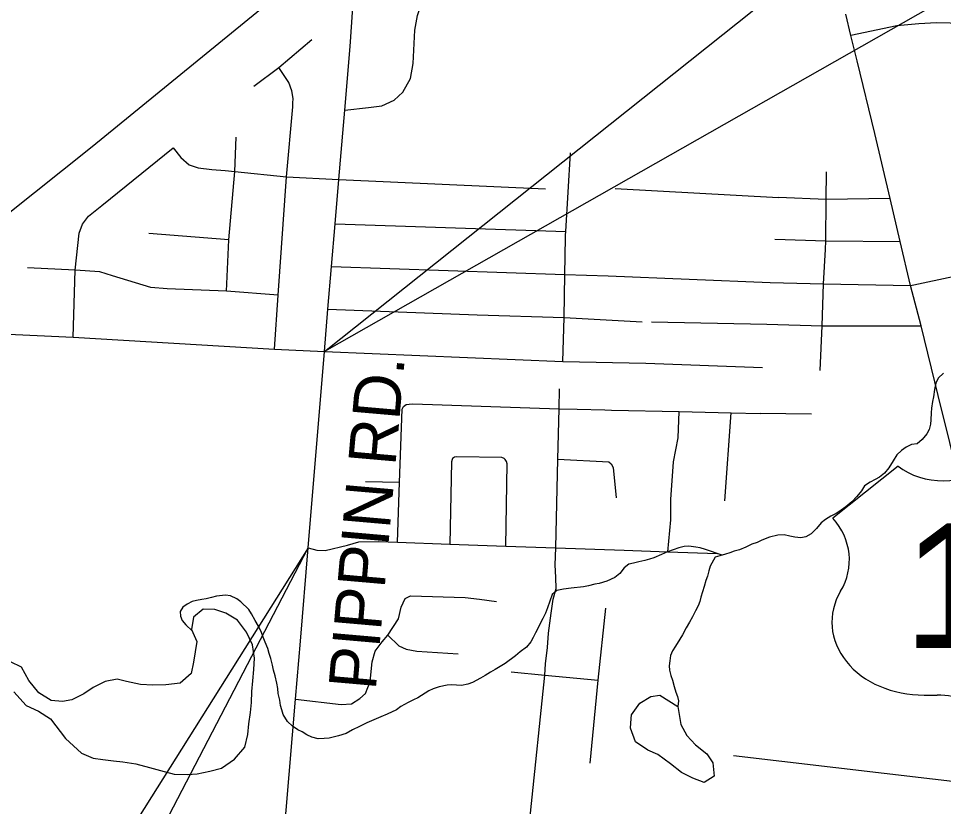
# Model space of a CAD drawing. Extents: x 0 to 34, y 0 to 22.
# Drawn here: x 4.878 to 5.853, y 18.558 to 19.39 of the extents above; entities that cross this region are included whole.
import ezdxf

# ---------------------------------------------------------------- set-up
doc = ezdxf.new("R2010")
doc.units = 0
for name, color, linetype in [('GM_X_County_Road', 7, 'Continuous'), ('GM_X_Interstate_Route', 7, 'Continuous'), ('GM_X_Minor_Lake', 7, 'Continuous'), ('GM_X_Minor_River', 7, 'Continuous'), ('GM_X_Township_ROW', 7, 'Continuous'), ('GM_X_Township_Subdivision', 7, 'Continuous'), ('GM_X_US_Location', 7, 'Continuous'), ('GM_X_US_Route', 7, 'Continuous'), ('GM_X_US_Shield', 7, 'Continuous'), ('RD_P_Text', 7, 'Continuous'), ('SH_Data', 7, 'Continuous')]:
    doc.layers.add(name, color=color, linetype=linetype)

msp = doc.modelspace()

# ---------------------------------------------------------------- linework, layer by layer
at = {"layer": 'GM_X_County_Road'}
for points in [[(5.22032, 19.27679), (5.22169, 19.29301), (5.22737, 19.36039), (5.23583, 19.48408), (5.24687, 19.56925), (5.2531, 19.59368), (5.26696, 19.62416), (5.29814, 19.67508), (5.31221, 19.7074), (5.32012, 19.73072), (5.32457, 19.76478), (5.32835, 19.81159), (5.32927, 19.82298)], [(5.22169, 19.29301), (5.24666, 19.29579), (5.26074, 19.29765), (5.27381, 19.30371), (5.28317, 19.31216), (5.29118, 19.32636), (5.29393, 19.34224), (5.29577, 19.37751), (5.29851, 19.39301), (5.30394, 19.40956), (5.31396, 19.4275), (5.32432, 19.4439), (5.33767, 19.45908), (5.35705, 19.47331), (5.60532, 19.65996), (5.61377, 19.66351), (5.62561, 19.66657), (5.64155, 19.66723), (5.7177, 19.66432)], [(5.15003, 18.43713), (5.16975, 18.67126), (5.17494, 18.73275), (5.18306, 18.83102), (5.20023, 19.03841), (5.20397, 19.0829), (5.20779, 19.12823), (5.21159, 19.17326), (5.21554, 19.22002), (5.22032, 19.27679)], [(4.72311, 18.96889), (4.8302, 18.963), (4.8342, 18.9639), (4.83656, 18.96426), (4.8395, 18.96616), (4.8421, 18.9698), (4.84348, 18.97638), (4.84261, 19.04558), (4.84288, 19.04886), (4.84374, 19.05095), (4.84521, 19.05293), (4.84851, 19.05588), (4.85379, 19.057), (4.85942, 19.057), (4.93528, 19.05337), (5.14755, 19.04076), (5.20023, 19.03841)]]:
    msp.add_lwpolyline(points, dxfattribs=at)
at = {"layer": 'GM_X_Interstate_Route'}
msp.add_lwpolyline([(4.36882, 18.49655), (4.39605, 18.53637), (4.4605, 18.66986), (4.5302, 18.81816), (4.56505, 18.88063), (4.60057, 18.93093), (4.64857, 18.98913), (4.70519, 19.04965), (4.77056, 19.1075), (4.95535, 19.25481), (5.23583, 19.48408)], dxfattribs=at)
at = {"layer": 'GM_X_Minor_Lake'}
for points in [[(4.92715, 18.62971), (4.94392, 18.61453), (4.95634, 18.60895), (4.96656, 18.6076), (4.97793, 18.60623), (4.98778, 18.60527), (5.00141, 18.60309), (5.01577, 18.59938), (5.02747, 18.5961), (5.04183, 18.59238), (5.05587, 18.59172), (5.06614, 18.59265), (5.07949, 18.59543), (5.09171, 18.5986), (5.10558, 18.60822), (5.11647, 18.62055), (5.11941, 18.63419), (5.1204, 18.6452), (5.12217, 18.65734), (5.12353, 18.66797), (5.12377, 18.67938), (5.12476, 18.69077), (5.12577, 18.70255), (5.1264, 18.71471), (5.12441, 18.72883), (5.11824, 18.74227), (5.10862, 18.75465), (5.09624, 18.76212), (5.08455, 18.76617), (5.0724, 18.76641), (5.06235, 18.75786), (5.06018, 18.74497), (5.06562, 18.7323), (5.06212, 18.71031)], [(5.06212, 18.71031), (5.0596, 18.69856), (5.04799, 18.68814), (5.03315, 18.68654), (5.01946, 18.68606), (5.00618, 18.68671), (4.99144, 18.69005), (4.98162, 18.69253), (4.96904, 18.69012), (4.95637, 18.68353), (4.94635, 18.67688), (4.93369, 18.67067), (4.92416, 18.66896), (4.91203, 18.66997), (4.89891, 18.67823), (4.88854, 18.69099), (4.88086, 18.70523), (4.8692, 18.71079)], [(4.87272, 18.67914), (4.88572, 18.6648), (4.8985, 18.65883), (4.91125, 18.65058), (4.92715, 18.62971)], [(5.52404, 18.65105), (5.52412, 18.65485), (5.53311, 18.66721), (5.54465, 18.67419), (5.55418, 18.67552), (5.57308, 18.66349)], [(5.57308, 18.66349), (5.57634, 18.64467), (5.58256, 18.63314), (5.59186, 18.62307), (5.60383, 18.61371), (5.61009, 18.60408), (5.61132, 18.59), (5.60092, 18.58337), (5.58886, 18.58817), (5.57683, 18.59412), (5.56523, 18.60309), (5.55213, 18.61286), (5.54159, 18.61763), (5.52847, 18.62626), (5.52307, 18.64081), (5.52404, 18.65105)]]:
    msp.add_lwpolyline(points, dxfattribs=at)
at = {"layer": 'GM_X_Minor_River'}
for points in [[(5.85352, 19.01542), (5.84772, 19.01021), (5.84534, 19.00493), (5.84406, 18.99811), (5.84277, 18.99053), (5.84191, 18.9856), (5.84063, 18.9784), (5.84053, 18.97346), (5.84, 18.96624), (5.83953, 18.96169), (5.83827, 18.95601), (5.8359, 18.95149), (5.83085, 18.94551), (5.82544, 18.94105), (5.81973, 18.94003), (5.81398, 18.93748), (5.80897, 18.93377), (5.80433, 18.9293), (5.8004, 18.92291), (5.79569, 18.9154), (5.79103, 18.90979), (5.78601, 18.9057), (5.7814, 18.90313), (5.77603, 18.90058), (5.76988, 18.89652), (5.76674, 18.89126), (5.76206, 18.88526), (5.75663, 18.87967), (5.75045, 18.87447), (5.74544, 18.87076), (5.74006, 18.86744), (5.73469, 18.86451), (5.72893, 18.8612), (5.7243, 18.85749), (5.71924, 18.85151), (5.71381, 18.84591), (5.70805, 18.8426), (5.70272, 18.84157), (5.69666, 18.84245), (5.69136, 18.84331), (5.68532, 18.84495), (5.67848, 18.84433)], [(5.67848, 18.84433), (5.66971, 18.84223), (5.66167, 18.83934), (5.65669, 18.83678), (5.65134, 18.83498), (5.64482, 18.83169), (5.63831, 18.82916), (5.63259, 18.82775), (5.628, 18.82594), (5.62342, 18.82451), (5.61731, 18.82273), (5.61234, 18.82131), (5.60722, 18.8119), (5.60598, 18.80698), (5.60435, 18.80131), (5.60273, 18.79677), (5.60108, 18.79034), (5.59907, 18.78468), (5.59744, 18.77901), (5.59621, 18.77446), (5.5946, 18.76993), (5.59183, 18.76466), (5.58867, 18.75826), (5.58552, 18.75262), (5.58198, 18.7466), (5.57803, 18.73945), (5.57528, 18.73457), (5.57058, 18.72743), (5.56744, 18.72255), (5.56545, 18.71765), (5.56457, 18.71196), (5.56408, 18.70664), (5.56437, 18.70207), (5.56577, 18.69634), (5.56757, 18.69136), (5.56934, 18.68486), (5.57111, 18.67874), (5.57292, 18.67414), (5.57396, 18.66955), (5.57308, 18.66349)], [(5.61987, 18.82348), (5.60226, 18.8295), (5.5966, 18.83113), (5.59206, 18.83198), (5.58487, 18.83288), (5.57993, 18.8326), (5.5742, 18.83119), (5.56235, 18.82687), (5.55584, 18.82395), (5.5478, 18.82069), (5.54321, 18.81926), (5.53825, 18.81784), (5.53215, 18.81644), (5.52643, 18.81503), (5.52147, 18.81399), (5.51645, 18.80991), (5.51178, 18.80391), (5.50676, 18.79983), (5.49833, 18.79581), (5.49031, 18.79331), (5.48574, 18.79264), (5.47887, 18.79087), (5.47353, 18.78984), (5.4606, 18.78858), (5.45261, 18.7876), (5.44537, 18.78622), (5.44072, 18.78175), (5.43793, 18.77496), (5.43551, 18.76778), (5.43349, 18.76211), (5.43072, 18.75646), (5.42282, 18.74141), (5.42045, 18.73651), (5.41808, 18.73199), (5.41341, 18.72638), (5.40685, 18.72119), (5.40183, 18.7171), (5.39104, 18.70895), (5.38028, 18.7027), (5.37567, 18.69975), (5.36991, 18.69644), (5.36491, 18.6935), (5.35647, 18.6891), (5.3515, 18.6873), (5.34502, 18.68591), (5.33971, 18.68601), (5.3344, 18.6865), (5.32984, 18.68621), (5.32146, 18.68448), (5.31496, 18.68232), (5.31036, 18.68013), (5.29882, 18.67276), (5.29422, 18.67056), (5.28848, 18.66802), (5.2808, 18.66361), (5.27617, 18.66027), (5.26659, 18.65552), (5.2597, 18.65262), (5.24515, 18.64644), (5.23747, 18.64241), (5.22981, 18.63914), (5.22328, 18.63509), (5.21526, 18.63258), (5.20534, 18.63012), (5.20002, 18.62984), (5.19356, 18.62959), (5.18714, 18.63124), (5.18188, 18.63363), (5.177, 18.63677), (5.17212, 18.63915), (5.1665, 18.64306), (5.16128, 18.64773), (5.15688, 18.65505), (5.15546, 18.66002), (5.15403, 18.66461), (5.15339, 18.67033), (5.15163, 18.67721), (5.15098, 18.68255), (5.14996, 18.68827), (5.14822, 18.69592), (5.14644, 18.70204), (5.14541, 18.70738), (5.14366, 18.71426), (5.14187, 18.71962), (5.14046, 18.72498), (5.13793, 18.73149), (5.13576, 18.73686), (5.13396, 18.74184), (5.13068, 18.74837), (5.12739, 18.75453), (5.12335, 18.76145), (5.12041, 18.76607), (5.11223, 18.77423), (5.10774, 18.77736), (5.10135, 18.78053), (5.09604, 18.78101), (5.08653, 18.78006), (5.08119, 18.77865), (5.07547, 18.77724), (5.0709, 18.77657), (5.06519, 18.77554)], [(5.06519, 18.77554), (5.06061, 18.77449), (5.05561, 18.77155), (5.051, 18.7686), (5.04825, 18.76409), (5.04853, 18.75914), (5.05033, 18.75454), (5.05404, 18.7499), (5.06078, 18.74358)]]:
    msp.add_lwpolyline(points, dxfattribs=at)
at = {"layer": 'GM_X_Township_ROW'}
msp.add_lwpolyline([(5.45471, 19.1612), (5.45494, 19.16517), (5.45975, 19.24795)], dxfattribs=at)
at = {"layer": 'GM_X_Township_Subdivision'}
for points in [[(6.45189, 19.30539), (6.39603, 19.31089), (6.35374, 19.31597), (6.33981, 19.31943), (6.32998, 19.3201), (6.31176, 19.31951), (6.27406, 19.31757), (6.25596, 19.31664), (6.24342, 19.31587), (6.23214, 19.31887), (6.21057, 19.3271), (6.17778, 19.33875), (6.17102, 19.34086), (6.15596, 19.34397), (6.01484, 19.36533), (5.98856, 19.36881), (5.9313, 19.37639), (5.87364, 19.38403), (5.8604, 19.38481), (5.84601, 19.38524), (5.82741, 19.38428), (5.80431, 19.38208), (5.75569, 19.37193)], [(5.12583, 19.31851), (5.15228, 19.33816), (5.18703, 19.36755)], [(5.16711, 19.30041), (5.16742, 19.30529), (5.16604, 19.31357), (5.16287, 19.32241), (5.15228, 19.33816)], [(5.14755, 19.04076), (5.15158, 19.09766), (5.16045, 19.22256), (5.16687, 19.29659), (5.16711, 19.30041)], [(5.09706, 19.10209), (5.09943, 19.15618), (5.10584, 19.2284), (5.10736, 19.26466)], [(4.93528, 19.05337), (4.9374, 19.12437), (4.94153, 19.16319), (4.94498, 19.17261), (4.95141, 19.18134), (4.96542, 19.1926), (5.0407, 19.25343)], [(5.0407, 19.25343), (5.04882, 19.24308), (5.05757, 19.23539), (5.06728, 19.23208), (5.08169, 19.23051), (5.0957, 19.22933), (5.10584, 19.2284), (5.16045, 19.22256), (5.21554, 19.22002)], [(5.72877, 19.14592), (5.72926, 19.15516), (5.72958, 19.19865), (5.72979, 19.22804)], [(5.21554, 19.22002), (5.43357, 19.20999)], [(5.50705, 19.21045), (5.67931, 19.20106)], [(5.79715, 19.19981), (5.72958, 19.19865), (5.67931, 19.20106)], [(5.21159, 19.17326), (5.45494, 19.16517)], [(5.09943, 19.15618), (5.01519, 19.16296)], [(5.45182, 19.02794), (5.45306, 19.07432), (5.45389, 19.11974), (5.45455, 19.15854), (5.45471, 19.1612)], [(5.67554, 19.15694), (5.72926, 19.15516), (5.80759, 19.15446)], [(5.72324, 19.01827), (5.72546, 19.06538), (5.72683, 19.1096), (5.72877, 19.14592)], [(5.15158, 19.09766), (5.09706, 19.10209), (5.03434, 19.10438), (5.01734, 19.10576), (4.97691, 19.11817), (4.96335, 19.1223), (4.9374, 19.12437), (4.88709, 19.12667)], [(5.20779, 19.12823), (5.45389, 19.11974), (5.49973, 19.11809), (5.67052, 19.11128)], [(5.82192, 19.10863), (5.89951, 19.12527), (5.94254, 19.13158), (5.96422, 19.13382), (5.97312, 19.13431), (6.00004, 19.133), (6.01744, 19.13107), (6.03428, 19.12678), (6.0514, 19.12085), (6.10516, 19.09437), (6.13514, 19.07381), (6.22325, 19.01337), (6.26853, 18.9823), (6.28732, 18.96426), (6.29939, 18.94984), (6.30735, 18.93744), (6.31365, 18.92015), (6.3373, 18.86857)], [(5.67052, 19.11128), (5.72683, 19.1096), (5.81863, 19.10793), (5.82192, 19.10863)], [(5.20397, 19.0829), (5.3614, 19.07722), (5.45306, 19.07432), (5.5356, 19.06981)], [(5.54533, 19.06979), (5.66691, 19.06732)], [(5.66691, 19.06732), (5.72546, 19.06538), (5.82967, 19.06556)], [(5.20023, 19.03841), (5.45182, 19.02794), (5.53921, 19.026)], [(5.53921, 19.026), (5.53921, 19.026), (5.66248, 19.02148)], [(5.40779, 18.42382), (5.41303, 18.49599), (5.41765, 18.55114), (5.43292, 18.69661), (5.43338, 18.70856), (5.43568, 18.72579), (5.43676, 18.74106), (5.43958, 18.76231), (5.44165, 18.77679), (5.44464, 18.78831), (5.4446, 18.79971), (5.44387, 18.81303), (5.44431, 18.83112), (5.44659, 18.92465), (5.44788, 18.97796), (5.44839, 18.99906)], [(5.27743, 18.83707), (5.27968, 18.90004), (5.28246, 18.97761), (5.28361, 18.98036), (5.28661, 18.98248), (5.28975, 18.98278), (5.29362, 18.98297), (5.44788, 18.97796), (5.46708, 18.97734), (5.496, 18.97669), (5.50319, 18.97653)], [(5.50319, 18.97653), (5.57454, 18.97493), (5.62945, 18.9737), (5.65991, 18.97302)], [(5.56255, 18.82692), (5.56559, 18.86064), (5.56582, 18.882), (5.56869, 18.92197), (5.57351, 18.94736), (5.57454, 18.97493)], [(5.62256, 18.88059), (5.62945, 18.9737)], [(5.71415, 18.97219), (5.65991, 18.97302)], [(5.39178, 18.83299), (5.39291, 18.91981), (5.39237, 18.92231), (5.3911, 18.92421), (5.38994, 18.92537), (5.38743, 18.92644), (5.34006, 18.9271), (5.33765, 18.92674), (5.33554, 18.92526), (5.33491, 18.92442), (5.33422, 18.92196), (5.33271, 18.8351)], [(5.44659, 18.92465), (5.50025, 18.92189), (5.50285, 18.91991), (5.505, 18.91605), (5.5082, 18.88404)], [(5.27968, 18.90004), (5.24375, 18.90075)], [(5.18306, 18.83102), (5.19226, 18.82874), (5.20097, 18.82847), (5.22464, 18.83383), (5.23649, 18.83728), (5.25736, 18.83778), (5.27743, 18.83707), (5.33271, 18.8351), (5.39178, 18.83299), (5.44431, 18.83112), (5.51637, 18.82856), (5.51641, 18.82856)], [(5.51641, 18.82856), (5.56255, 18.82692), (5.61485, 18.82505)], [(5.16975, 18.67126), (5.2179, 18.6656), (5.22892, 18.66652), (5.23765, 18.67203), (5.24362, 18.67732), (5.24845, 18.68995), (5.25074, 18.71086), (5.25396, 18.72211), (5.26108, 18.73199), (5.26705, 18.73911), (5.27854, 18.75634), (5.28142, 18.76854), (5.28548, 18.77754), (5.29118, 18.78046), (5.34884, 18.77885), (5.36377, 18.77679), (5.38168, 18.77464)], [(5.48071, 18.6038), (5.48921, 18.69133), (5.49702, 18.76737)], [(5.26705, 18.73911), (5.27866, 18.72759), (5.28652, 18.72431), (5.29782, 18.72207), (5.34133, 18.71924)], [(5.39731, 18.70029), (5.43292, 18.69661), (5.48921, 18.69133)], [(5.94959, 18.57423), (5.63182, 18.61171)]]:
    msp.add_lwpolyline(points, dxfattribs=at)
at = {"layer": 'GM_X_US_Route'}
for points in [[(5.76227, 19.34507), (5.75569, 19.37193), (5.75049, 19.39446)], [(5.81863, 19.10793), (5.80759, 19.15446), (5.79715, 19.19981), (5.78104, 19.26842), (5.76227, 19.34507)], [(5.84787, 18.99207), (5.82967, 19.06556), (5.81863, 19.10793)], [(5.93403, 18.64411), (5.9336, 18.64601), (5.84787, 18.99207)]]:
    msp.add_lwpolyline(points, dxfattribs=at)
at = {"layer": 'GM_X_US_Shield'}
for p, q in [((5.8054, 18.91748), (5.73673, 18.86255)), ((5.83286, 18.67578), (5.8466, 18.67578))]:
    msp.add_line(p, q, dxfattribs=at)
for centre, major_axis, start_param, end_param in [((5.85346, 18.95671), (-0.06866, 0), 0.795399, 2.346194), ((5.65799, 18.81844), (0.09613, 0), 5.838949, 6.894067), ((5.83179, 18.75268), (0.09613, 0), 2.702327, 4.723529), ((5.8466, 18.62085), (-0.06866, 0), 3.785094, 4.712389)]:
    msp.add_ellipse(centre, major_axis=major_axis, ratio=0.8, start_param=start_param, end_param=end_param, dxfattribs=at)
at = {"layer": 'RD_P_Text'}
for points in [[(5.85491, 19.41058), (5.20023, 19.03841), (5.85491, 19.55982), (5.85491, 19.41058)], [(4.72469, 17.94932), (5.18306, 18.83102), (4.72469, 18.10243), (4.72469, 17.94932)]]:
    msp.add_lwpolyline(points, dxfattribs=at)
at = {"layer": 'SH_Data'}
msp.add_line((5.18306, 18.83102), (5.20023, 19.03841), dxfattribs=at)

# ---------------------------------------------------------------- texts
at = {"layer": 'GM_X_US_Location'}
msp.add_text('127', height=0.000189, rotation=0.00001, dxfattribs=at).set_placement((5.84337, 18.75184))
at = {"layer": 'GM_X_US_Shield'}
msp.add_text('127', height=0.131836, dxfattribs=at).set_placement((5.81146, 18.72522))
at = {"layer": 'RD_P_Text'}
msp.add_text('PIPPIN RD.', height=0.05, rotation=85, dxfattribs=at).set_placement((5.25437, 18.67994))

doc.saveas('drawing.dxf')
